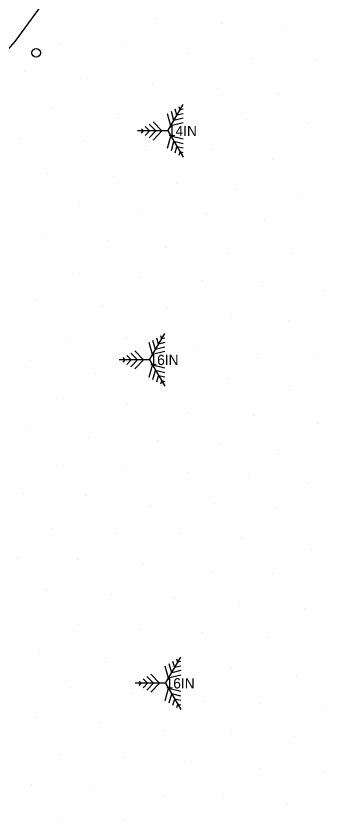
# Model space of a CAD drawing. Extents: x 1732346 to 1733076, y 467730 to 468633.
# Drawn here: x 1732572.2 to 1732626.3, y 468189.6 to 468330.7 of the extents above; entities that cross this region are included whole.
import ezdxf

# ---------------------------------------------------------------- set-up
doc = ezdxf.new("R2010")
doc.units = 0
for name, color, linetype in [('Default', 7, 'Continuous'), ('S_Ground_SpotElevation', 7, 'Continuous'), ('S_Roadway_Edge_Pavement', 7, 'Continuous'), ('S_Text', 7, 'Continuous'), ('S_Traffic_Posts', 7, 'Continuous'), ('S_Trees_Conifer_Pay', 7, 'Continuous')]:
    doc.layers.add(name, color=color, linetype=linetype)

# ---------------------------------------------------------------- blocks, each defined once
blk = doc.blocks.new('POINT_DISPLAY')
at = {"layer": 'Default'}
blk.add_line((0, 0), (0, 0), dxfattribs=at)

msp = doc.modelspace()

# ---------------------------------------------------------------- linework, layer by layer
at = {"layer": 'S_Roadway_Edge_Pavement'}
msp.add_lwpolyline([(1732491.02, 468251.22), (1732497.44, 468255.62), (1732503.86, 468260.03), (1732508.23, 468263.02), (1732516.03, 468269.28), (1732520.4, 468272.79), (1732527.92, 468279.38), (1732530.62, 468281.75), (1732537.79, 468288.72), (1732543.83, 468294.59), (1732550.69, 468301.87), (1732557.48, 468309.07), (1732563.95, 468316.69), (1732570.43, 468324.31), (1732572.05, 468326.23), (1732577.91, 468334.33)], dxfattribs=at)
at = {"layer": 'S_Traffic_Posts'}
msp.add_circle((1732575.73, 468324.23), 0.749, dxfattribs=at)
at = {"layer": 'S_Trees_Conifer_Pay'}
for p, q in [((1732598.79, 468310.53), (1732601.45, 468315.14)), ((1732600.38, 468313.29), (1732600.08, 468314.34)), ((1732600.92, 468314.21), (1732600.77, 468314.74)), ((1732601.45, 468314.34), (1732600.92, 468314.21)), ((1732599.32, 468311.45), (1732598.71, 468313.55)), ((1732599.85, 468312.37), (1732599.4, 468313.95)), ((1732601.45, 468313.55), (1732600.38, 468313.29)), ((1732596.66, 468310.53), (1732595.52, 468311.71)), ((1732597.72, 468310.53), (1732596.2, 468312.11)), ((1732601.45, 468311.97), (1732599.32, 468311.45)), ((1732601.45, 468312.77), (1732599.85, 468312.37)), ((1732598.79, 468310.53), (1732593.46, 468310.53)), ((1732594.53, 468310.53), (1732594.15, 468310.92)), ((1732594.15, 468310.13), (1732594.53, 468310.53)), ((1732595.59, 468310.53), (1732594.83, 468311.31)), ((1732594.83, 468309.73), (1732595.59, 468310.53)), ((1732595.52, 468309.34), (1732596.66, 468310.53)), ((1732596.2, 468308.94), (1732597.72, 468310.53)), ((1732598.79, 468310.53), (1732601.45, 468305.91)), ((1732598.71, 468307.5), (1732599.32, 468309.6)), ((1732601.45, 468309.08), (1732599.32, 468309.6)), ((1732599.4, 468307.1), (1732599.85, 468308.68)), ((1732601.45, 468308.28), (1732599.85, 468308.68)), ((1732600.08, 468306.7), (1732600.38, 468307.76)), ((1732601.45, 468307.5), (1732600.38, 468307.76)), ((1732600.77, 468306.31), (1732600.92, 468306.84)), ((1732601.45, 468306.7), (1732600.92, 468306.84)), ((1732595.57, 468270.4), (1732598.23, 468275.01)), ((1732596.1, 468271.32), (1732595.49, 468273.43)), ((1732596.63, 468272.24), (1732596.18, 468273.82)), ((1732597.16, 468273.17), (1732596.86, 468274.22)), ((1732598.23, 468273.43), (1732597.16, 468273.17)), ((1732597.7, 468274.09), (1732597.55, 468274.62)), ((1732598.23, 468274.22), (1732597.7, 468274.09)), ((1732598.23, 468272.64), (1732596.63, 468272.24)), ((1732591.31, 468270.4), (1732590.93, 468270.8)), ((1732592.37, 468270.4), (1732591.61, 468271.19)), ((1732593.44, 468270.4), (1732592.3, 468271.59)), ((1732594.5, 468270.4), (1732592.98, 468271.98)), ((1732598.23, 468271.85), (1732596.1, 468271.32)), ((1732595.57, 468270.4), (1732590.24, 468270.4)), ((1732590.93, 468270.01), (1732591.31, 468270.4)), ((1732591.61, 468269.61), (1732592.37, 468270.4)), ((1732592.3, 468269.21), (1732593.44, 468270.4)), ((1732592.98, 468268.82), (1732594.5, 468270.4)), ((1732595.49, 468267.37), (1732596.1, 468269.48)), ((1732595.57, 468270.4), (1732598.23, 468265.79)), ((1732598.23, 468268.95), (1732596.1, 468269.48)), ((1732596.18, 468266.98), (1732596.63, 468268.55)), ((1732598.23, 468268.16), (1732596.63, 468268.55)), ((1732596.86, 468266.58), (1732597.16, 468267.63)), ((1732598.23, 468267.37), (1732597.16, 468267.63)), ((1732597.55, 468266.18), (1732597.7, 468266.71)), ((1732598.23, 468266.58), (1732597.7, 468266.71)), ((1732598.39, 468213.72), (1732601.05, 468218.33)), ((1732599.46, 468215.56), (1732599, 468217.14)), ((1732599.98, 468216.49), (1732599.68, 468217.54)), ((1732600.52, 468217.41), (1732600.37, 468217.94)), ((1732601.05, 468217.54), (1732600.52, 468217.41)), ((1732598.92, 468214.64), (1732598.31, 468216.75)), ((1732601.05, 468215.96), (1732599.46, 468215.56)), ((1732601.05, 468216.75), (1732599.98, 468216.49)), ((1732595.2, 468213.72), (1732594.44, 468214.51)), ((1732596.26, 468213.72), (1732595.12, 468214.91)), ((1732597.32, 468213.72), (1732595.8, 468215.3)), ((1732601.05, 468215.17), (1732598.92, 468214.64)), ((1732598.39, 468213.72), (1732593.07, 468213.72)), ((1732594.13, 468213.72), (1732593.75, 468214.12)), ((1732593.75, 468213.33), (1732594.13, 468213.72)), ((1732594.44, 468212.93), (1732595.2, 468213.72)), ((1732595.12, 468212.53), (1732596.26, 468213.72)), ((1732595.8, 468212.14), (1732597.32, 468213.72)), ((1732598.31, 468210.69), (1732598.92, 468212.8)), ((1732598.39, 468213.72), (1732601.05, 468209.11)), ((1732601.05, 468212.27), (1732598.92, 468212.8)), ((1732599, 468210.3), (1732599.46, 468211.87)), ((1732601.05, 468211.48), (1732599.46, 468211.87)), ((1732599.68, 468209.9), (1732599.98, 468210.95)), ((1732601.05, 468210.69), (1732599.98, 468210.95)), ((1732600.37, 468209.5), (1732600.52, 468210.03)), ((1732601.05, 468209.9), (1732600.52, 468210.03))]:
    msp.add_line(p, q, dxfattribs=at)

# ---------------------------------------------------------------- block references
at = {"layer": 'S_Ground_SpotElevation'}
for p in [(1732596.82, 468330.22), (1732608.23, 468329.32), (1732619.47, 468329.03), (1732579.71, 468325.81), (1732590.9, 468325.25), (1732602.21, 468324.06), (1732613.5, 468323.24), (1732624.44, 468322.99), (1732573.74, 468320.87), (1732584.73, 468319.72), (1732596.04, 468318.76), (1732607.4, 468318.03), (1732618.24, 468317.09), (1732578.71, 468314.71), (1732590.06, 468313.5), (1732600.58, 468313.55), (1732612.55, 468312.47), (1732623.19, 468311.85), (1732572.71, 468309.29), (1732584.08, 468308.77), (1732594.81, 468307.91), (1732606.57, 468307.35), (1732617.09, 468305.56), (1732577.75, 468303.1), (1732589.31, 468302.61), (1732600.29, 468301.28), (1732610.63, 468300.29), (1732621.96, 468299.64), (1732583.11, 468297.77), (1732605.63, 468296.07), (1732594.11, 468295.88), (1732615.76, 468295.02), (1732576.81, 468291.61), (1732588.31, 468291.32), (1732598.43, 468290.15), (1732609.6, 468289.1), (1732620.81, 468289.02), (1732582.08, 468285.51), (1732593.58, 468284.9), (1732604.92, 468284.32), (1732615.33, 468283.34), (1732626.06, 468282.53), (1732576, 468281.03), (1732587.28, 468279.71), (1732598.71, 468279.65), (1732609.67, 468278.11), (1732619.87, 468277.27), (1732581.01, 468274.33), (1732591.5, 468274.18), (1732603.69, 468273), (1732614.52, 468271.51), (1732625.06, 468271.45), (1732574.74, 468270.24), (1732586.05, 468268.01), (1732597.25, 468267.73), (1732609.18, 468267.13), (1732620.04, 468265.95), (1732579.21, 468263.57), (1732591.79, 468262.84), (1732602.32, 468261.27), (1732613.85, 468260.57), (1732625.06, 468259.3), (1732574.04, 468258.08), (1732584.81, 468256.84), (1732596.93, 468256.33), (1732608.21, 468255.59), (1732618.11, 468254.67), (1732579.32, 468251.85), (1732590.81, 468251.02), (1732602.24, 468250.59), (1732613.04, 468249.89), (1732623.48, 468248.71), (1732573.57, 468247.07), (1732584.37, 468246.66), (1732595.72, 468244.72), (1732606.89, 468245.17), (1732618.01, 468244.3), (1732578.38, 468240.86), (1732589.95, 468240.02), (1732600.88, 468239.94), (1732611.6, 468239.11), (1732623.89, 468237.15), (1732572.47, 468235.84), (1732583.03, 468235.5), (1732594.45, 468234.65), (1732606.26, 468233.28), (1732617.1, 468232.98), (1732577.44, 468230.11), (1732588.95, 468229.29), (1732599.95, 468228.73), (1732611.18, 468227.69), (1732622.71, 468226.81), (1732583.06, 468224.07), (1732594.1, 468223.19), (1732604.93, 468222.69), (1732616.59, 468221.69), (1732576.14, 468219.21), (1732587.78, 468218.32), (1732598.83, 468217.32), (1732609.98, 468216.28), (1732621.36, 468215.03), (1732581.81, 468213.07), (1732592.51, 468212.02), (1732604.78, 468210.5), (1732615.09, 468210.25), (1732626.29, 468208.87), (1732576.01, 468207.69), (1732586.74, 468206.91), (1732597.97, 468205.43), (1732609.74, 468205.13), (1732620.88, 468204.35), (1732580.12, 468201.25), (1732591.41, 468200.68), (1732602.92, 468200), (1732614.89, 468198.72), (1732625.93, 468198.33), (1732574.96, 468195.9), (1732585.57, 468195.76), (1732597.89, 468194.07), (1732608.29, 468193.8), (1732619.77, 468192.67), (1732580.2, 468190.18), (1732591.3, 468189.6)]:
    msp.add_blockref('POINT_DISPLAY', p, dxfattribs=at)

# ---------------------------------------------------------------- texts
at = {"layer": 'S_Text'}
for s, p in [('14IN', (1732598.79, 468309.62)), ('16IN', (1732595.57, 468269.5)), ('16IN', (1732598.39, 468212.82))]:
    msp.add_text(s, height=1.8, dxfattribs=at).set_placement(p)

doc.saveas('drawing.dxf')
